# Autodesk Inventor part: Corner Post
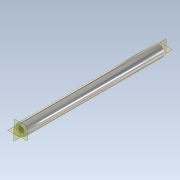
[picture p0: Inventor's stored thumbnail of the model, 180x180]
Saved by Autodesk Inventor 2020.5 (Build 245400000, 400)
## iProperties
LastFilename: FCG_Part.ipt
DataBaseUnit: MM
Created: 2023-05
Part Number: Corner Post
Material: 250 Grade
Document SubType Name: Modeling
Designer: A. Bennett
Mass: 35.8331 g
Surface Area: 29.1888 cm^2
Volume: 4.45782 cm^3
Density: 8.03824 g/cm^3
Appearance: Chrome - Polished
Author: A. Bennett
Revision Number: -
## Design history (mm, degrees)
sketch "Sketch10"
  geometry: C1 r 4 at (0, 0); 1 further point
  constraints: 1 centre point, 1 coincident
  dimensions: "d25" = 8 diameter of C1
extrude "Extrusion7" new body sketch "Sketch10" distance "d26" = 97; taper "d27" = 0 deg
chamfer "Chamfer1" distance "d28" = 0.25; stored, may be unused: second distance "d29" = 2, angle "d30" = 45 deg
sketch "Sketch11"
  geometry: C1 r 4 at (0, 0) reference; 2 further points
  constraints: 1 coincident
hole "Hole2" sketch "Sketch11" at (0, 0) diameter "d31" = 4.134; stored, may be unused: countersink angle "d35" = 90 deg, drill point angle "d37" = 118 deg; dims "d32" = 12, "d33" = 5, "d34" = 2, "d36" = 15
sketch "Sketch12"
  geometry: C1 r 4 at (0, 0) reference; 2 further points
  constraints: 1 coincident
hole "Hole3" sketch "Sketch12" at (0, 0) diameter "d38" = 4.134; stored, may be unused: countersink angle "d42" = 90 deg, drill point angle "d44" = 118 deg; dims "d39" = 12, "d40" = 5, "d41" = 2, "d43" = 15
body "Solid7"
other parameters: "OD" = 1 [user parameter], "OAL" = 1 [user parameter]
